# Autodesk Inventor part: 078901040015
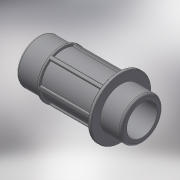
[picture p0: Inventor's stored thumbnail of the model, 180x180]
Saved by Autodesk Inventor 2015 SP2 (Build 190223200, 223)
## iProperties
Created: 2018-02
Part Number: 078901040015
Material: Generic
Description: PLASSON THREADED MALE ADAPTOR 40-1.1/2"
Document SubType Name: Modeling
Designer: KIM
Density: 1 g/cm^3
Appearance: Default
Author: KIM
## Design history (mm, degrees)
derived "078901.ipt"
feature "Solid1::078901.ipt"
tag "TaggingFeature1"
body "Solid1"
other parameters: "d4" = 2.39015, "d14" = 3.82424, "d15" = 1.91212, "d17" = 0, "d20" = 360 deg, "d40" = 22, "d41" = 47.803, "d45" = 52.5833, "d46" = 33.4621, "d47" = 2.2, "d85" = 0.47803, "d103" = 23, "d104" = 58, "d105" = 0.47803, "R_" = 47.803, "E_" = 58, "l_2" = 22
